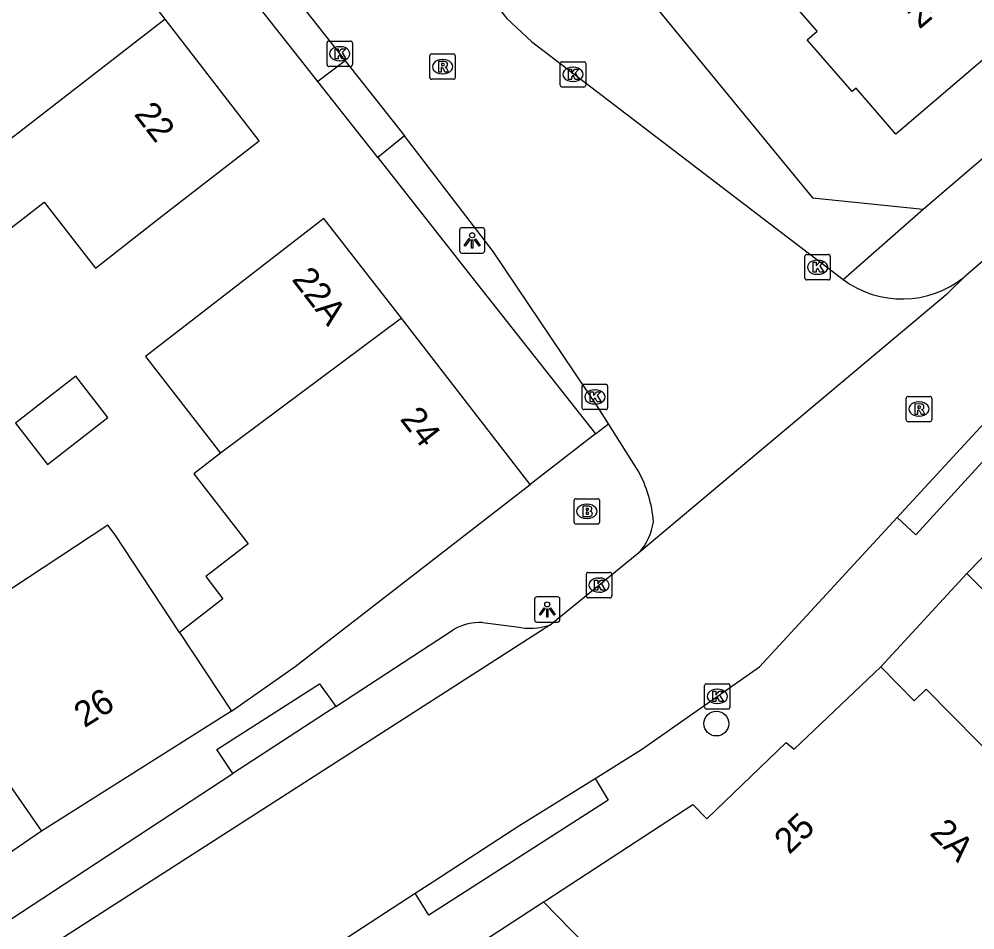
# Model space of a CAD drawing. Extents: x 161772 to 163123, y 383092 to 383917.
# Drawn here: x 162273.18 to 162310.8, y 383362.61 to 383398.46 of the extents above; entities that cross this region are included whole.
import ezdxf

# ---------------------------------------------------------------- set-up
doc = ezdxf.new("R2010")
doc.units = 0
for name, color, linetype in [('IMGEO_Boom', 7, 'Continuous'), ('IMGEO_Brandkraan', 7, 'Continuous'), ('IMGEO_Kolk', 7, 'Continuous'), ('IMGEO_Lichtpunt', 7, 'Continuous'), ('IMGEO_Pand', 7, 'Continuous'), ('IMGEO_Pand_nummerreeks', 7, 'Continuous'), ('IMGEO_Rijbaan_lokaal_open', 7, 'Continuous'), ('IMGEO_Rioolput', 7, 'Continuous'), ('IMGEO_Voetpad_open', 7, 'Continuous')]:
    doc.layers.add(name, color=color, linetype=linetype)

msp = doc.modelspace()

# ---------------------------------------------------------------- linework, layer by layer
at = {"layer": 'IMGEO_Boom'}
msp.add_circle((162300.619, 383370.728), 0.489, dxfattribs=at)
at = {"layer": 'IMGEO_Brandkraan'}
for p, q in [((162295.021, 383378.654), (162295.021, 383379.506)), ((162295.096, 383379.58), (162295.948, 383379.58)), ((162295.509, 383379.36), (162295.534, 383379.36)), ((162296.022, 383379.506), (162296.022, 383378.654)), ((162295.948, 383378.58), (162295.096, 383378.58)), ((162295.532, 383378.8), (162295.507, 383378.8))]:
    msp.add_line(p, q, dxfattribs=at)
for points in [[(162295.021, 383378.654), (162295.021, 383379.506)], [(162295.096, 383379.58), (162295.948, 383379.58)], [(162296.022, 383379.506), (162296.022, 383378.654)], [(162295.369, 383379.28), (162295.369, 383378.88), (162295.582, 383378.88)], [(162295.6, 383379.28), (162295.369, 383379.28)], [(162295.548, 383379.199), (162295.494, 383379.199), (162295.494, 383379.123)], [(162295.494, 383379.123), (162295.547, 383379.123)], [(162295.556, 383379.047), (162295.494, 383379.047), (162295.494, 383378.966)], [(162295.494, 383378.966), (162295.556, 383378.966)], [(162295.948, 383378.58), (162295.096, 383378.58)]]:
    msp.add_lwpolyline(points, dxfattribs=at)
for centre, radius, start, end in [((162295.098, 383379.504), 0.0765, 91.552, 178.448), ((162295.098, 383379.504), 0.0765, 91.552, 178.448), ((162295.946, 383379.504), 0.0765, 1.552, 88.448), ((162295.946, 383379.504), 0.0765, 1.552, 88.448), ((162295.549, 383379.161), 0.0379, 267.8285, 90.9355), ((162295.557, 383379.006), 0.0404, 269.8759, 90.5077), ((162295.604, 383379.135), 0.145, 59.4692, 91.5367), ((162295.629, 383379.182), 0.0922, 285.5137, 58.1501), ((162295.634, 383378.99), 0.105, 301.3115, 78.989), ((162295.098, 383378.656), 0.0765, 181.552, 268.448), ((162295.098, 383378.656), 0.0765, 181.552, 268.448), ((162295.588, 383379.131), 0.251, 268.6676, 293.5347), ((162295.946, 383378.656), 0.0765, 271.552, 358.448), ((162295.946, 383378.656), 0.0765, 271.552, 358.448)]:
    msp.add_arc(centre, radius, start, end, dxfattribs=at)
for centre, major_axis, ratio, start_param, end_param in [((162295.508, 383379.08), (-0.387, 0.002), 0.722429, 4.712389, 7.853982), ((162295.533, 383379.08), (-0.39, 0.002), 0.717154, 1.570796, 4.712389)]:
    msp.add_ellipse(centre, major_axis=major_axis, ratio=ratio, start_param=start_param, end_param=end_param, dxfattribs=at)
at = {"layer": 'IMGEO_Kolk'}
for p, q in [((162285.296, 383396.669), (162285.296, 383397.521)), ((162285.371, 383397.595), (162286.223, 383397.595)), ((162285.784, 383397.375), (162285.809, 383397.375)), ((162286.297, 383397.521), (162286.297, 383396.669)), ((162286.223, 383396.595), (162285.371, 383396.595)), ((162285.807, 383396.815), (162285.782, 383396.815)), ((162294.475, 383395.858), (162294.475, 383396.71)), ((162294.55, 383396.784), (162295.402, 383396.784)), ((162295.476, 383396.71), (162295.476, 383395.858)), ((162294.963, 383396.564), (162294.988, 383396.564)), ((162294.986, 383396.004), (162294.961, 383396.004)), ((162295.402, 383395.784), (162294.55, 383395.784)), ((162304.103, 383388.267), (162304.103, 383389.119)), ((162304.178, 383389.193), (162305.03, 383389.193)), ((162305.104, 383389.119), (162305.104, 383388.267)), ((162304.591, 383388.973), (162304.616, 383388.973)), ((162304.614, 383388.413), (162304.589, 383388.413)), ((162305.03, 383388.193), (162304.178, 383388.193)), ((162295.337, 383383.162), (162295.337, 383384.014)), ((162295.412, 383384.088), (162296.264, 383384.088)), ((162295.825, 383383.868), (162295.85, 383383.868)), ((162296.338, 383384.014), (162296.338, 383383.162)), ((162296.264, 383383.088), (162295.412, 383383.088)), ((162295.848, 383383.308), (162295.823, 383383.308)), ((162295.579, 383376.677), (162296.431, 383376.677)), ((162295.504, 383375.751), (162295.504, 383376.603)), ((162295.992, 383376.457), (162296.017, 383376.457)), ((162296.505, 383376.603), (162296.505, 383375.751)), ((162296.015, 383375.897), (162295.99, 383375.897)), ((162296.431, 383375.677), (162295.579, 383375.677)), ((162300.154, 383371.371), (162300.154, 383372.223)), ((162300.229, 383372.297), (162301.081, 383372.297)), ((162301.155, 383372.223), (162301.155, 383371.371)), ((162300.642, 383372.077), (162300.667, 383372.077)), ((162300.665, 383371.517), (162300.64, 383371.517)), ((162301.081, 383371.297), (162300.229, 383371.297))]:
    msp.add_line(p, q, dxfattribs=at)
for points in [[(162285.296, 383396.669), (162285.296, 383397.521)], [(162285.371, 383397.595), (162286.223, 383397.595)], [(162286.297, 383397.521), (162286.297, 383396.669)], [(162285.617, 383397.295), (162285.74, 383397.295), (162285.74, 383397.144), (162285.87, 383397.295), (162286.034, 383397.295), (162285.888, 383397.144), (162286.041, 383396.895), (162285.889, 383396.895), (162285.804, 383397.059), (162285.74, 383396.992), (162285.74, 383396.895), (162285.617, 383396.895), (162285.617, 383397.295)], [(162286.223, 383396.595), (162285.371, 383396.595)], [(162294.475, 383395.858), (162294.475, 383396.71)], [(162294.55, 383396.784), (162295.402, 383396.784)], [(162295.476, 383396.71), (162295.476, 383395.858)], [(162294.796, 383396.484), (162294.919, 383396.484), (162294.919, 383396.333), (162295.049, 383396.484), (162295.213, 383396.484), (162295.067, 383396.333), (162295.22, 383396.084), (162295.068, 383396.084), (162294.983, 383396.248), (162294.919, 383396.181), (162294.919, 383396.084), (162294.796, 383396.084), (162294.796, 383396.484)], [(162295.402, 383395.784), (162294.55, 383395.784)], [(162304.103, 383388.267), (162304.103, 383389.119)], [(162304.178, 383389.193), (162305.03, 383389.193)], [(162305.104, 383389.119), (162305.104, 383388.267)], [(162304.424, 383388.893), (162304.547, 383388.893), (162304.547, 383388.742), (162304.677, 383388.893), (162304.841, 383388.893), (162304.695, 383388.742), (162304.848, 383388.493), (162304.696, 383388.493), (162304.611, 383388.657), (162304.547, 383388.59), (162304.547, 383388.493), (162304.424, 383388.493), (162304.424, 383388.893)], [(162305.03, 383388.193), (162304.178, 383388.193)], [(162295.337, 383383.162), (162295.337, 383384.014)], [(162295.412, 383384.088), (162296.264, 383384.088)], [(162296.338, 383384.014), (162296.338, 383383.162)], [(162295.658, 383383.788), (162295.781, 383383.788), (162295.781, 383383.637), (162295.911, 383383.788), (162296.075, 383383.788), (162295.929, 383383.637), (162296.082, 383383.388), (162295.93, 383383.388), (162295.845, 383383.552), (162295.781, 383383.485), (162295.781, 383383.388), (162295.658, 383383.388), (162295.658, 383383.788)], [(162296.264, 383383.088), (162295.412, 383383.088)], [(162295.579, 383376.677), (162296.431, 383376.677)], [(162295.504, 383375.751), (162295.504, 383376.603)], [(162295.825, 383376.377), (162295.948, 383376.377), (162295.948, 383376.226), (162296.078, 383376.377), (162296.242, 383376.377), (162296.096, 383376.226), (162296.249, 383375.977), (162296.097, 383375.977), (162296.012, 383376.141), (162295.948, 383376.074), (162295.948, 383375.977), (162295.825, 383375.977), (162295.825, 383376.377)], [(162296.505, 383376.603), (162296.505, 383375.751)], [(162296.431, 383375.677), (162295.579, 383375.677)], [(162300.154, 383371.371), (162300.154, 383372.223)], [(162300.229, 383372.297), (162301.081, 383372.297)], [(162301.155, 383372.223), (162301.155, 383371.371)], [(162300.475, 383371.997), (162300.598, 383371.997), (162300.598, 383371.846), (162300.728, 383371.997), (162300.892, 383371.997), (162300.746, 383371.846), (162300.899, 383371.597), (162300.747, 383371.597), (162300.662, 383371.761), (162300.598, 383371.694), (162300.598, 383371.597), (162300.475, 383371.597), (162300.475, 383371.997)], [(162301.081, 383371.297), (162300.229, 383371.297)]]:
    msp.add_lwpolyline(points, dxfattribs=at)
for centre, start, end in [((162285.373, 383397.519), 91.552, 178.448), ((162285.373, 383397.519), 91.552, 178.448), ((162286.221, 383397.519), 1.552, 88.448), ((162286.221, 383397.519), 1.552, 88.448), ((162285.373, 383396.671), 181.552, 268.448), ((162285.373, 383396.671), 181.552, 268.448), ((162286.221, 383396.671), 271.552, 358.448), ((162286.221, 383396.671), 271.552, 358.448), ((162294.552, 383396.708), 91.552, 178.448), ((162294.552, 383396.708), 91.552, 178.448), ((162295.4, 383396.708), 1.552, 88.448), ((162295.4, 383396.708), 1.552, 88.448), ((162294.552, 383395.86), 181.552, 268.448), ((162294.552, 383395.86), 181.552, 268.448), ((162295.4, 383395.86), 271.552, 358.448), ((162295.4, 383395.86), 271.552, 358.448), ((162304.18, 383389.117), 91.552, 178.448), ((162304.18, 383389.117), 91.552, 178.448), ((162305.028, 383389.117), 1.552, 88.448), ((162305.028, 383389.117), 1.552, 88.448), ((162304.18, 383388.269), 181.552, 268.448), ((162304.18, 383388.269), 181.552, 268.448), ((162305.028, 383388.269), 271.552, 358.448), ((162305.028, 383388.269), 271.552, 358.448), ((162295.414, 383384.012), 91.552, 178.448), ((162295.414, 383384.012), 91.552, 178.448), ((162296.262, 383384.012), 1.552, 88.448), ((162296.262, 383384.012), 1.552, 88.448), ((162295.414, 383383.164), 181.552, 268.448), ((162295.414, 383383.164), 181.552, 268.448), ((162296.262, 383383.164), 271.552, 358.448), ((162296.262, 383383.164), 271.552, 358.448), ((162295.581, 383376.601), 91.552, 178.448), ((162295.581, 383376.601), 91.552, 178.448), ((162296.429, 383376.601), 1.552, 88.448), ((162296.429, 383376.601), 1.552, 88.448), ((162295.581, 383375.753), 181.552, 268.448), ((162295.581, 383375.753), 181.552, 268.448), ((162296.429, 383375.753), 271.552, 358.448), ((162296.429, 383375.753), 271.552, 358.448), ((162300.231, 383372.221), 91.552, 178.448), ((162300.231, 383372.221), 91.552, 178.448), ((162301.079, 383372.221), 1.552, 88.448), ((162301.079, 383372.221), 1.552, 88.448), ((162300.231, 383371.373), 181.552, 268.448), ((162300.231, 383371.373), 181.552, 268.448), ((162301.079, 383371.373), 271.552, 358.448), ((162301.079, 383371.373), 271.552, 358.448)]:
    msp.add_arc(centre, 0.0765, start, end, dxfattribs=at)
for centre, major_axis, ratio, start_param, end_param in [((162285.783, 383397.095), (-0.387, 0.002), 0.722429, 4.712389, 7.853982), ((162285.808, 383397.095), (-0.39, 0.002), 0.717154, 1.570796, 4.712389), ((162294.962, 383396.284), (-0.387, 0.002), 0.722429, 4.712389, 7.853982), ((162294.987, 383396.284), (-0.39, 0.002), 0.717154, 1.570796, 4.712389), ((162304.59, 383388.693), (-0.387, 0.002), 0.722429, 4.712389, 7.853982), ((162304.615, 383388.693), (-0.39, 0.002), 0.717154, 1.570796, 4.712389), ((162295.824, 383383.588), (-0.387, 0.002), 0.722429, 4.712389, 7.853982), ((162295.849, 383383.588), (-0.39, 0.002), 0.717154, 1.570796, 4.712389), ((162295.991, 383376.177), (-0.387, 0.002), 0.722429, 4.712389, 7.853982), ((162296.016, 383376.177), (-0.39, 0.002), 0.717154, 1.570796, 4.712389), ((162300.641, 383371.797), (-0.387, 0.002), 0.722429, 4.712389, 7.853982), ((162300.666, 383371.797), (-0.39, 0.002), 0.717154, 1.570796, 4.712389)]:
    msp.add_ellipse(centre, major_axis=major_axis, ratio=ratio, start_param=start_param, end_param=end_param, dxfattribs=at)
at = {"layer": 'IMGEO_Lichtpunt'}
for p, q in [((162291.412, 383390.248), (162290.604, 383390.248)), ((162291.412, 383390.248), (162290.604, 383390.248)), ((162290.51, 383390.153), (162290.51, 383389.346)), ((162290.51, 383390.153), (162290.51, 383389.346)), ((162291.506, 383389.346), (162291.506, 383390.153)), ((162291.506, 383389.346), (162291.506, 383390.153)), ((162290.604, 383389.252), (162291.412, 383389.252)), ((162290.604, 383389.252), (162291.412, 383389.252)), ((162293.466, 383375.623), (162293.466, 383374.816)), ((162293.466, 383375.623), (162293.466, 383374.816)), ((162294.368, 383375.718), (162293.56, 383375.718)), ((162294.368, 383375.718), (162293.56, 383375.718)), ((162294.462, 383374.816), (162294.462, 383375.623)), ((162294.462, 383374.816), (162294.462, 383375.623)), ((162293.56, 383374.722), (162294.368, 383374.722)), ((162293.56, 383374.722), (162294.368, 383374.722))]:
    msp.add_line(p, q, dxfattribs=at)
for points in [[(162290.884, 383389.817), (162290.923, 383389.789), (162290.735, 383389.527), (162290.697, 383389.554), (162290.884, 383389.817)], [(162291.096, 383389.789), (162291.134, 383389.816), (162291.321, 383389.554), (162291.282, 383389.526), (162291.096, 383389.789)], [(162290.986, 383389.769), (162291.033, 383389.769), (162291.033, 383389.447), (162290.986, 383389.447), (162290.986, 383389.769)], [(162293.84, 383375.287), (162293.879, 383375.259), (162293.691, 383374.997), (162293.653, 383375.024), (162293.84, 383375.287)], [(162293.942, 383375.239), (162293.989, 383375.239), (162293.989, 383374.917), (162293.942, 383374.917), (162293.942, 383375.239)], [(162294.052, 383375.259), (162294.09, 383375.286), (162294.277, 383375.024), (162294.238, 383374.996), (162294.052, 383375.259)]]:
    msp.add_lwpolyline(points, dxfattribs=at)
for centre in [(162291.009, 383389.951), (162293.965, 383375.421)]:
    msp.add_circle(centre, 0.0994, dxfattribs=at)
for centre, start, end in [((162290.604, 383390.153), 90, 180), ((162290.604, 383390.153), 90, 180), ((162291.412, 383390.153), 0, 90), ((162291.412, 383390.153), 0, 90), ((162290.604, 383389.346), 180, 270), ((162290.604, 383389.346), 180, 270), ((162291.412, 383389.346), 270, 0), ((162291.412, 383389.346), 270, 360), ((162293.56, 383375.623), 90, 180), ((162293.56, 383375.623), 90, 180), ((162294.368, 383375.623), 0, 90), ((162294.368, 383375.623), 0, 90), ((162293.56, 383374.816), 180, 270), ((162293.56, 383374.816), 180, 270), ((162294.368, 383374.816), 270, 0), ((162294.368, 383374.816), 270, 360)]:
    msp.add_arc(centre, 0.0946, start, end, dxfattribs=at)
at = {"layer": 'IMGEO_Pand'}
for points in [[(162311.221, 383406.379), (162308.871, 383404.359), (162309.655, 383403.446), (162311.827, 383400.918), (162312.165, 383401.209), (162313.853, 383399.245), (162314.21, 383397.56), (162312.88, 383396.42), (162311.27, 383396.99), (162307.685, 383393.934), (162306.117, 383395.743), (162305.959, 383395.605), (162304.191, 383397.643), (162304.584, 383397.984), (162301.103, 383402.001), (162303.996, 383404.482), (162302.83, 383405.844)], [(162278.92, 383398.452), (162275.219, 383403.23), (162271.272, 383400.161), (162268.885, 383398.311), (162271.059, 383395.505), (162266.811, 383392.214), (162265.932, 383391.532), (162267.452, 383389.57)], [(162267.452, 383389.57), (162269.156, 383387.37), (162270.035, 383388.052), (162274.166, 383391.257), (162276.186, 383388.654), (162278.67, 383390.612), (162282.622, 383393.674), (162278.92, 383398.452)], [(162278.92, 383398.452), (162268.331, 383390.251), (162267.452, 383389.57)], [(162288.222, 383386.685), (162285.176, 383390.616), (162281.224, 383387.554), (162278.15, 383385.172), (162281.096, 383381.37)], [(162288.222, 383386.685), (162281.096, 383381.37)], [(162293.293, 383380.139), (162288.222, 383386.685)], [(162273.819, 383383.167), (162273.033, 383382.558), (162274.292, 383380.931), (162276.671, 383382.774), (162275.411, 383384.4), (162273.819, 383383.167)], [(162281.096, 383381.37), (162280.05, 383380.559), (162282.185, 383377.803), (162280.522, 383376.514), (162281.197, 383375.642), (162279.486, 383374.316)], [(162281.53, 383371.212), (162284.036, 383372.968), (162293.293, 383380.139)], [(162279.486, 383374.316), (162276.955, 383378.161), (162276.666, 383378.534), (162269.13, 383373.573), (162271.202, 383370.596), (162274.058, 383366.492)], [(162279.486, 383374.316), (162281.53, 383371.212)], [(162293.817, 383363.705), (162293.909, 383363.765), (162299.693, 383367.539), (162300.246, 383366.973), (162303.367, 383369.986), (162303.684, 383369.717), (162307.098, 383372.957)], [(162307.098, 383372.957), (162308.41, 383371.629), (162308.879, 383372.08), (162311.937, 383368.986), (162311.467, 383368.534), (162316.664, 383363.284)], [(162281.53, 383371.212), (162274.058, 383366.492)], [(162286.046, 383358.641), (162293.817, 383363.705)], [(162305.263, 383351.995), (162302.446, 383354.878), (162302.175, 383355.155), (162299.275, 383358.122), (162293.817, 383363.705)]]:
    msp.add_lwpolyline(points, dxfattribs=at)
at = {"layer": 'IMGEO_Rijbaan_lokaal_open'}
for points in [[(162255.096, 383445.775), (162255.329, 383445.472), (162265.082, 383433.068), (162273.478, 383422.429), (162282.487, 383410.964), (162292.366, 383398.478), (162293.345, 383397.58), (162303.185, 383390.06), (162305.607, 383388.209)], [(162278.881, 383405.852), (162285.837, 383397.046), (162286.012, 383396.824)], [(162286.012, 383396.824), (162288.343, 383393.869)], [(162317.816, 383394.703), (162314.712, 383392.04), (162310.37, 383388.302)], [(162296.373, 383382.529), (162295.966, 383383.173), (162291.831, 383389.315), (162288.343, 383393.869)], [(162297.572, 383377.466), (162309.749, 383387.68), (162310.37, 383388.302)], [(162307.742, 383378.84), (162312.426, 383383.912)], [(162297.545, 383380.677), (162296.373, 383382.529)], [(162310.48, 383376.63), (162315.096, 383381.379)], [(162295.846, 383368.569), (162297.678, 383369.705), (162302.316, 383372.966), (162307.742, 383378.84)], [(162294.06, 383374.608), (162297.572, 383377.466)], [(162311.396, 383375.713), (162310.48, 383376.63)], [(162294.06, 383374.608), (162247.678, 383344.816)], [(162288.762, 383364.047), (162289.496, 383364.525), (162292.841, 383366.706), (162295.846, 383368.569)], [(162280.472, 383358.642), (162288.762, 383364.047)]]:
    msp.add_lwpolyline(points, dxfattribs=at)
for centre, radius, start, end in [((162307.928, 383391.335), 3.893, 233.3995, 308.8377), ((162293.242, 383378.31), 4.911, 4.1523, 28.8118), ((162296.065, 383378.914), 2.089, 316.1453, 353.1952)]:
    msp.add_arc(centre, radius, start, end, dxfattribs=at)
at = {"layer": 'IMGEO_Rioolput'}
for p, q in [((162289.341, 383396.164), (162289.341, 383397.016)), ((162289.416, 383397.09), (162290.268, 383397.09)), ((162290.342, 383397.016), (162290.342, 383396.164)), ((162289.829, 383396.87), (162289.854, 383396.87)), ((162289.852, 383396.31), (162289.827, 383396.31)), ((162290.268, 383396.09), (162289.416, 383396.09)), ((162308.095, 383382.683), (162308.095, 383383.535)), ((162308.17, 383383.609), (162309.022, 383383.609)), ((162309.096, 383383.535), (162309.096, 383382.683)), ((162308.583, 383383.389), (162308.608, 383383.389)), ((162308.606, 383382.829), (162308.581, 383382.829)), ((162309.022, 383382.609), (162308.17, 383382.609))]:
    msp.add_line(p, q, dxfattribs=at)
for points in [[(162289.341, 383396.164), (162289.341, 383397.016)], [(162289.416, 383397.09), (162290.268, 383397.09)], [(162290.342, 383397.016), (162290.342, 383396.164)], [(162289.93, 383396.788), (162289.678, 383396.79), (162289.678, 383396.39)], [(162289.856, 383396.709), (162289.802, 383396.709), (162289.802, 383396.628)], [(162289.802, 383396.628), (162289.854, 383396.628)], [(162289.678, 383396.39), (162289.802, 383396.39), (162289.802, 383396.552), (162289.813, 383396.552)], [(162289.86, 383396.523), (162289.931, 383396.39), (162290.071, 383396.39), (162290.006, 383396.516)], [(162290.268, 383396.09), (162289.416, 383396.09)], [(162308.095, 383382.683), (162308.095, 383383.535)], [(162308.17, 383383.609), (162309.022, 383383.609)], [(162309.096, 383383.535), (162309.096, 383382.683)], [(162308.684, 383383.307), (162308.432, 383383.309), (162308.432, 383382.909)], [(162308.432, 383382.909), (162308.556, 383382.909), (162308.556, 383383.071), (162308.567, 383383.071)], [(162308.61, 383383.228), (162308.556, 383383.228), (162308.556, 383383.147)], [(162308.556, 383383.147), (162308.608, 383383.147)], [(162308.614, 383383.042), (162308.685, 383382.909), (162308.825, 383382.909), (162308.76, 383383.035)], [(162309.022, 383382.609), (162308.17, 383382.609)]]:
    msp.add_lwpolyline(points, dxfattribs=at)
for centre, radius, start, end in [((162289.418, 383397.014), 0.0765, 91.552, 178.448), ((162289.418, 383397.014), 0.0765, 91.552, 178.448), ((162290.266, 383397.014), 0.0765, 1.552, 88.448), ((162290.266, 383397.014), 0.0765, 1.552, 88.448), ((162289.838, 383396.817), 0.19, 274.7715, 282.9687), ((162289.862, 383396.613), 0.0964, 77.0061, 93.1865), ((162289.876, 383396.67), 0.0378, 276.6634, 79.6772), ((162289.929, 383396.678), 0.109, 350.3612, 89.416), ((162289.927, 383396.678), 0.112, 277.5842, 350.9817), ((162289.812, 383396.499), 0.0533, 26.0293, 88.6989), ((162289.911, 383396.463), 0.108, 29.5134, 73.7905), ((162289.418, 383396.166), 0.0765, 181.552, 268.448), ((162289.418, 383396.166), 0.0765, 181.552, 268.448), ((162290.266, 383396.166), 0.0765, 271.552, 358.448), ((162290.266, 383396.166), 0.0765, 271.552, 358.448), ((162308.172, 383383.533), 0.0765, 91.552, 178.448), ((162308.172, 383383.533), 0.0765, 91.552, 178.448), ((162309.02, 383383.533), 0.0765, 1.552, 88.448), ((162309.02, 383383.533), 0.0765, 1.552, 88.448), ((162308.566, 383383.018), 0.0533, 26.0293, 88.6989), ((162308.592, 383383.336), 0.19, 274.7715, 282.9687), ((162308.616, 383383.132), 0.0964, 77.0061, 93.1865), ((162308.63, 383383.189), 0.0378, 276.6634, 79.6772), ((162308.683, 383383.197), 0.109, 350.3612, 89.416), ((162308.681, 383383.197), 0.112, 277.5842, 350.9817), ((162308.665, 383382.982), 0.108, 29.5134, 73.7905), ((162308.172, 383382.685), 0.0765, 181.552, 268.448), ((162308.172, 383382.685), 0.0765, 181.552, 268.448), ((162309.02, 383382.685), 0.0765, 271.552, 358.448), ((162309.02, 383382.685), 0.0765, 271.552, 358.448)]:
    msp.add_arc(centre, radius, start, end, dxfattribs=at)
for centre, major_axis, ratio, start_param, end_param in [((162289.828, 383396.59), (-0.387, 0.002), 0.722429, 4.712389, 7.853982), ((162289.853, 383396.59), (-0.39, 0.002), 0.717154, 1.570796, 4.712389), ((162308.582, 383383.109), (-0.387, 0.002), 0.722429, 4.712389, 7.853982), ((162308.607, 383383.109), (-0.39, 0.002), 0.717154, 1.570796, 4.712389)]:
    msp.add_ellipse(centre, major_axis=major_axis, ratio=ratio, start_param=start_param, end_param=end_param, dxfattribs=at)
at = {"layer": 'IMGEO_Voetpad_open'}
for points in [[(162257.454, 383448.811), (162257.925, 383449.194), (162258.467, 383448.473), (162281.694, 383418.863), (162284.418, 383415.396), (162294.261, 383403.773), (162297.953, 383399.3), (162304.407, 383391.419), (162308.762, 383390.978)], [(162308.762, 383390.978), (162315.013, 383396.326), (162363.856, 383438.295), (162364.058, 383438.278), (162367.39, 383441.216)], [(162284.939, 383396.009), (162277.817, 383405.027)], [(162286.012, 383396.824), (162284.939, 383396.009)], [(162287.296, 383393.011), (162284.939, 383396.009)], [(162288.343, 383393.869), (162287.296, 383393.011)], [(162287.296, 383393.011), (162291.001, 383388.301), (162295.862, 383382.133)], [(162305.607, 383388.209), (162308.762, 383390.978)], [(162312.426, 383383.912), (162313.161, 383383.294), (162308.468, 383378.157), (162307.742, 383378.84)], [(162295.862, 383382.133), (162296.373, 383382.529)], [(162295.862, 383382.133), (162293.293, 383380.139)], [(162310.48, 383376.63), (162307.098, 383372.957)], [(162285.641, 383371.405), (162290.302, 383374.444)], [(162291.42, 383374.707), (162292.765, 383374.537)], [(162281.593, 383368.76), (162280.952, 383369.701), (162285.004, 383372.297), (162285.641, 383371.405)], [(162285.641, 383371.405), (162285.269, 383371.162)], [(162285.269, 383371.162), (162282.64, 383369.447)], [(162282.64, 383369.447), (162281.593, 383368.76)], [(162248.509, 383347.068), (162254.518, 383351.008), (162257.543, 383352.991), (162281.593, 383368.76)], [(162295.846, 383368.569), (162296.355, 383367.718), (162289.304, 383363.189), (162288.762, 383364.047)], [(162274.058, 383366.492), (162272.473, 383365.4)]]:
    msp.add_lwpolyline(points, dxfattribs=at)
for centre, radius, start, end in [((162291.345, 383372.519), 2.19, 88.0338, 118.4415), ((162293.282, 383376.953), 2.471, 257.9222, 288.3541)]:
    msp.add_arc(centre, radius, start, end, dxfattribs=at)

# ---------------------------------------------------------------- texts
at = {"layer": 'IMGEO_Pand_nummerreeks'}
for s, rotation, p in [('24', 40.4451, (162308.615, 383398.039)), ('22', 307.7634, (162277.671, 383394.71)), ('22A', 307.7692, (162283.88, 383388.207)), ('24', 307.7634, (162288.139, 383382.709)), ('26', 32.2804, (162275.75, 383370.541)), ('25', 43.9917, (162303.491, 383365.545)), ('2A', 314.679, (162308.983, 383366.386))]:
    msp.add_text(s, height=1, rotation=rotation, dxfattribs=at).set_placement(p)

doc.saveas('drawing.dxf')
